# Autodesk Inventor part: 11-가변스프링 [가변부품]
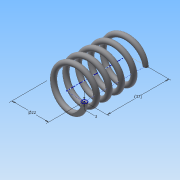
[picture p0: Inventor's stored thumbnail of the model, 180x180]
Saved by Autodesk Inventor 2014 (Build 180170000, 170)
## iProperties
Created: 2015-09
Part Number: 11-가변스프링 [가변부품]
Material: 강철, 탄소
Document SubType Name: Modeling
Designer: study
Density: 7.87 g/cm^3
Appearance: 반연마
Mass: 18.9156 g
Surface Area: 32.5757 cm^2
Volume: 2.40351 cm^3
Author: study
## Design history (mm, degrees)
sketch "스케치1"
  geometry: L1 (0, 0)-(11, 0); L2 (11, 0)-(11, 39.945); L3 (11, 39.945)-(0, 39.945); L4 (0, 39.945)-(0, 0); C1 r 1.5 at (11, 0)
  constraints: 8 end point, 2 parallel, 1 centre point, 1 coincident, 1 horizontal, 1 perpendicular
  dimensions: "d0" = 22 diameter of L2 L4; "d1" = 39.9455 distance of L1.end L2.end (derived); "d2" = 3 diameter of C1
feature "코일1" pitch "d3" = 10; turns "d5" = 5; dims "d4" = 39.9455 (= d1), "d6" = 0, angle "d7" = 90 deg, angle "d8" = 90 deg, "d9" = 0, "d10" = 0
node "작업 평면1"
sketch "스케치2"
  geometry: L1 (-12.5, 0)-(-9.5, 0) reference; 1 further point
  constraints: 1 horizontal alignment
extrude "돌출1" cut sketch "스케치2" stored distance "d12" = 10; taper "d13" = 0 deg
node "작업 평면2"
sketch "스케치3"
  geometry: L1 (-9.5, 0)-(-12.5, 0) reference; 1 further point
  constraints: 1 horizontal alignment
extrude "돌출2" cut sketch "스케치3" stored distance "d15" = 10; taper "d16" = 0 deg
node "솔리드1"
node "절단 모서리 투영1"
node "절단 모서리 투영2"
other parameters: "d11" = 0, "d14" = 39.9455 (= d1)
